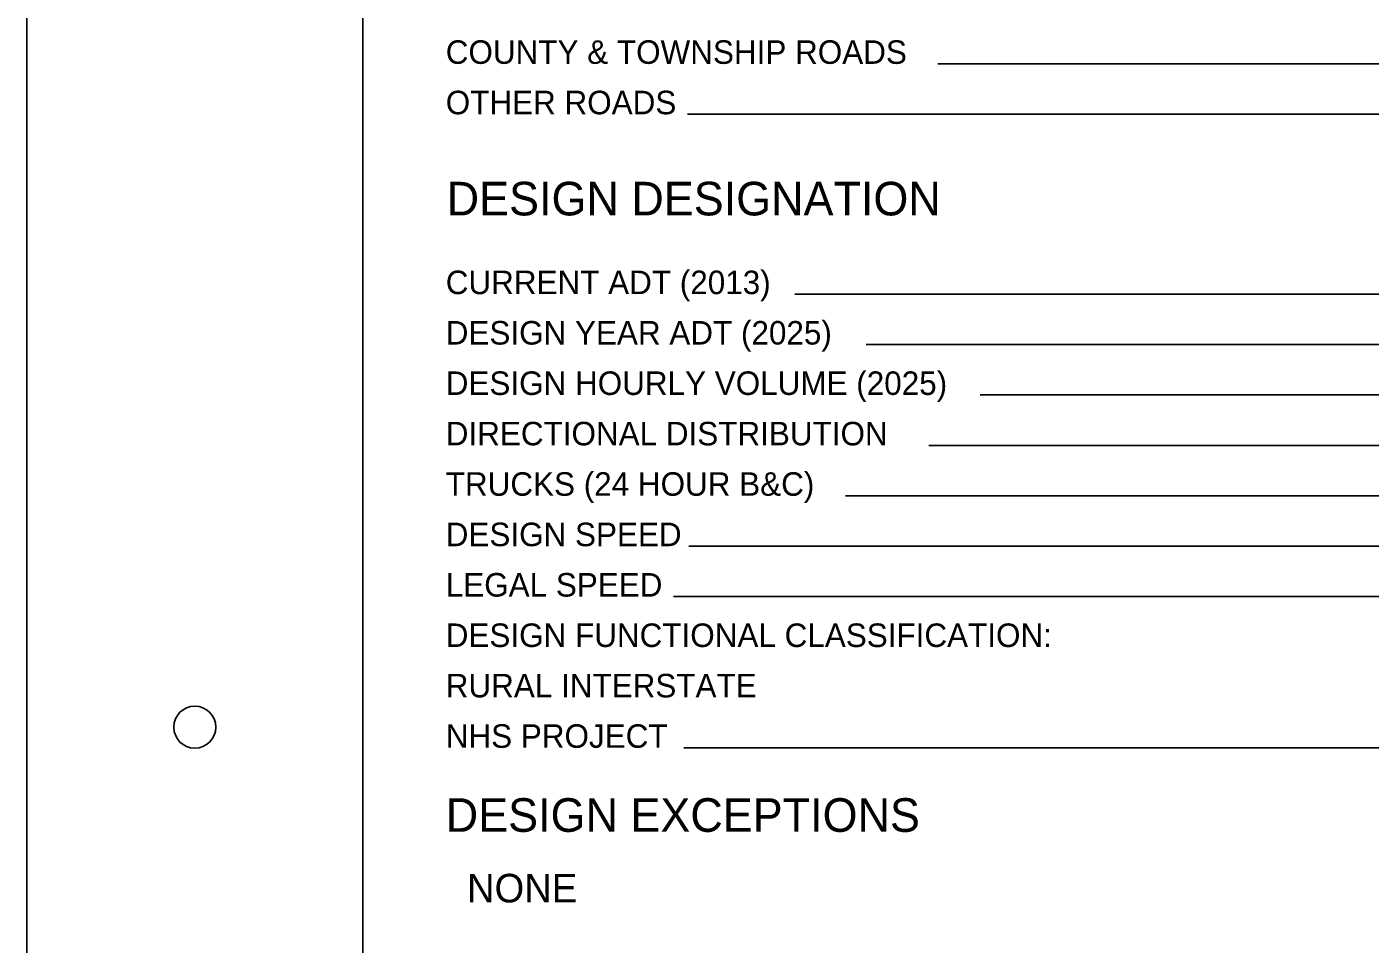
# Model space of a CAD drawing. Extents: x 0.4 to 34.4, y -2.1 to 19.9.
# Drawn here: x 0.4 to 8.4, y 3.39 to 8.85 of the extents above; entities that cross this region are included whole.
import ezdxf

# ---------------------------------------------------------------- set-up
doc = ezdxf.new("R2010")
doc.units = 0
for name, color, linetype in [('SH_Border', 7, 'Continuous'), ('SH_Cut_Line', 7, 'Continuous'), ('SH_Data', 7, 'Continuous')]:
    doc.layers.add(name, color=color, linetype=linetype)

msp = doc.modelspace()

# ---------------------------------------------------------------- linework, layer by layer
at = {"layer": 'SH_Border'}
msp.add_lwpolyline([(2.4001, 19.4357), (33.9001, 19.4357), (33.9001, -1.5643), (2.4001, -1.5643)], close=True, dxfattribs=at)
msp.add_circle((1.4001, 4.6857), 0.125, dxfattribs=at)
at = {"layer": 'SH_Cut_Line'}
msp.add_lwpolyline([(0.4001, -2.0643), (34.4001, -2.0643), (34.4001, 19.9357), (0.4001, 19.9357)], close=True, dxfattribs=at)
at = {"layer": 'SH_Data'}
for p, q in [((8.6001, 8.6332), (5.8241, 8.6332)), ((8.6001, 8.3332), (4.3349, 8.3332)), ((8.5425, 7.2627), (4.9738, 7.2627)), ((8.537, 6.9627), (5.3989, 6.9627)), ((8.537, 6.6627), (6.076, 6.6627)), ((8.537, 6.3627), (5.7713, 6.3627)), ((8.537, 6.0627), (5.2747, 6.0627)), ((8.537, 5.7627), (4.3418, 5.7627)), ((8.537, 5.4627), (4.2515, 5.4627)), ((8.537, 4.5627), (4.3117, 4.5627))]:
    msp.add_line(p, q, dxfattribs=at)

# ---------------------------------------------------------------- texts
for s, height, p in [('COUNTY & TOWNSHIP ROADS', 0.14, (2.8945, 8.6332)), ('OTHER ROADS', 0.14, (2.8945, 8.3332)), ('DESIGN DESIGNATION', 0.2, (2.9001, 7.7312)), ('CURRENT ADT (2013)', 0.14, (2.8945, 7.2627)), ('DESIGN YEAR ADT (2025)', 0.14, (2.8945, 6.9627)), ('DESIGN HOURLY VOLUME (2025)', 0.14, (2.8945, 6.6627)), ('DIRECTIONAL DISTRIBUTION', 0.14, (2.8945, 6.3627)), ('TRUCKS (24 HOUR B&C)', 0.14, (2.8945, 6.0627)), ('DESIGN SPEED', 0.14, (2.8945, 5.7627)), ('LEGAL SPEED', 0.14, (2.8945, 5.4627)), ('DESIGN FUNCTIONAL CLASSIFICATION:', 0.14, (2.8945, 5.1627)), ('RURAL INTERSTATE                                ', 0.14, (2.8945, 4.8627)), ('NHS PROJECT', 0.14, (2.8945, 4.5627)), ('DESIGN EXCEPTIONS', 0.2, (2.8945, 4.0627)), ('  NONE                                   ', 0.17, (2.8945, 3.6427))]:
    msp.add_text(s, height=height, dxfattribs=at).set_placement(p)

doc.saveas('drawing.dxf')
